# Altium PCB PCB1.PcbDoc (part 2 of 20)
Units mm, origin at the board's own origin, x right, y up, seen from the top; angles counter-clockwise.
Board outline 294.51 x 138.18 mm, 12 copper layers (Top Layer 1 _Signal, L2_GND, L3_Signals, L4_GND, L5_POWER, L6_Signals, L7_GND, L8_Signals, L9_GND, L10_POWER, L11_GND, Bottom Layer_Signals), stack 1.788 mm thick; 1254 components, 836 nets, 5699 pads, 2073 vias.
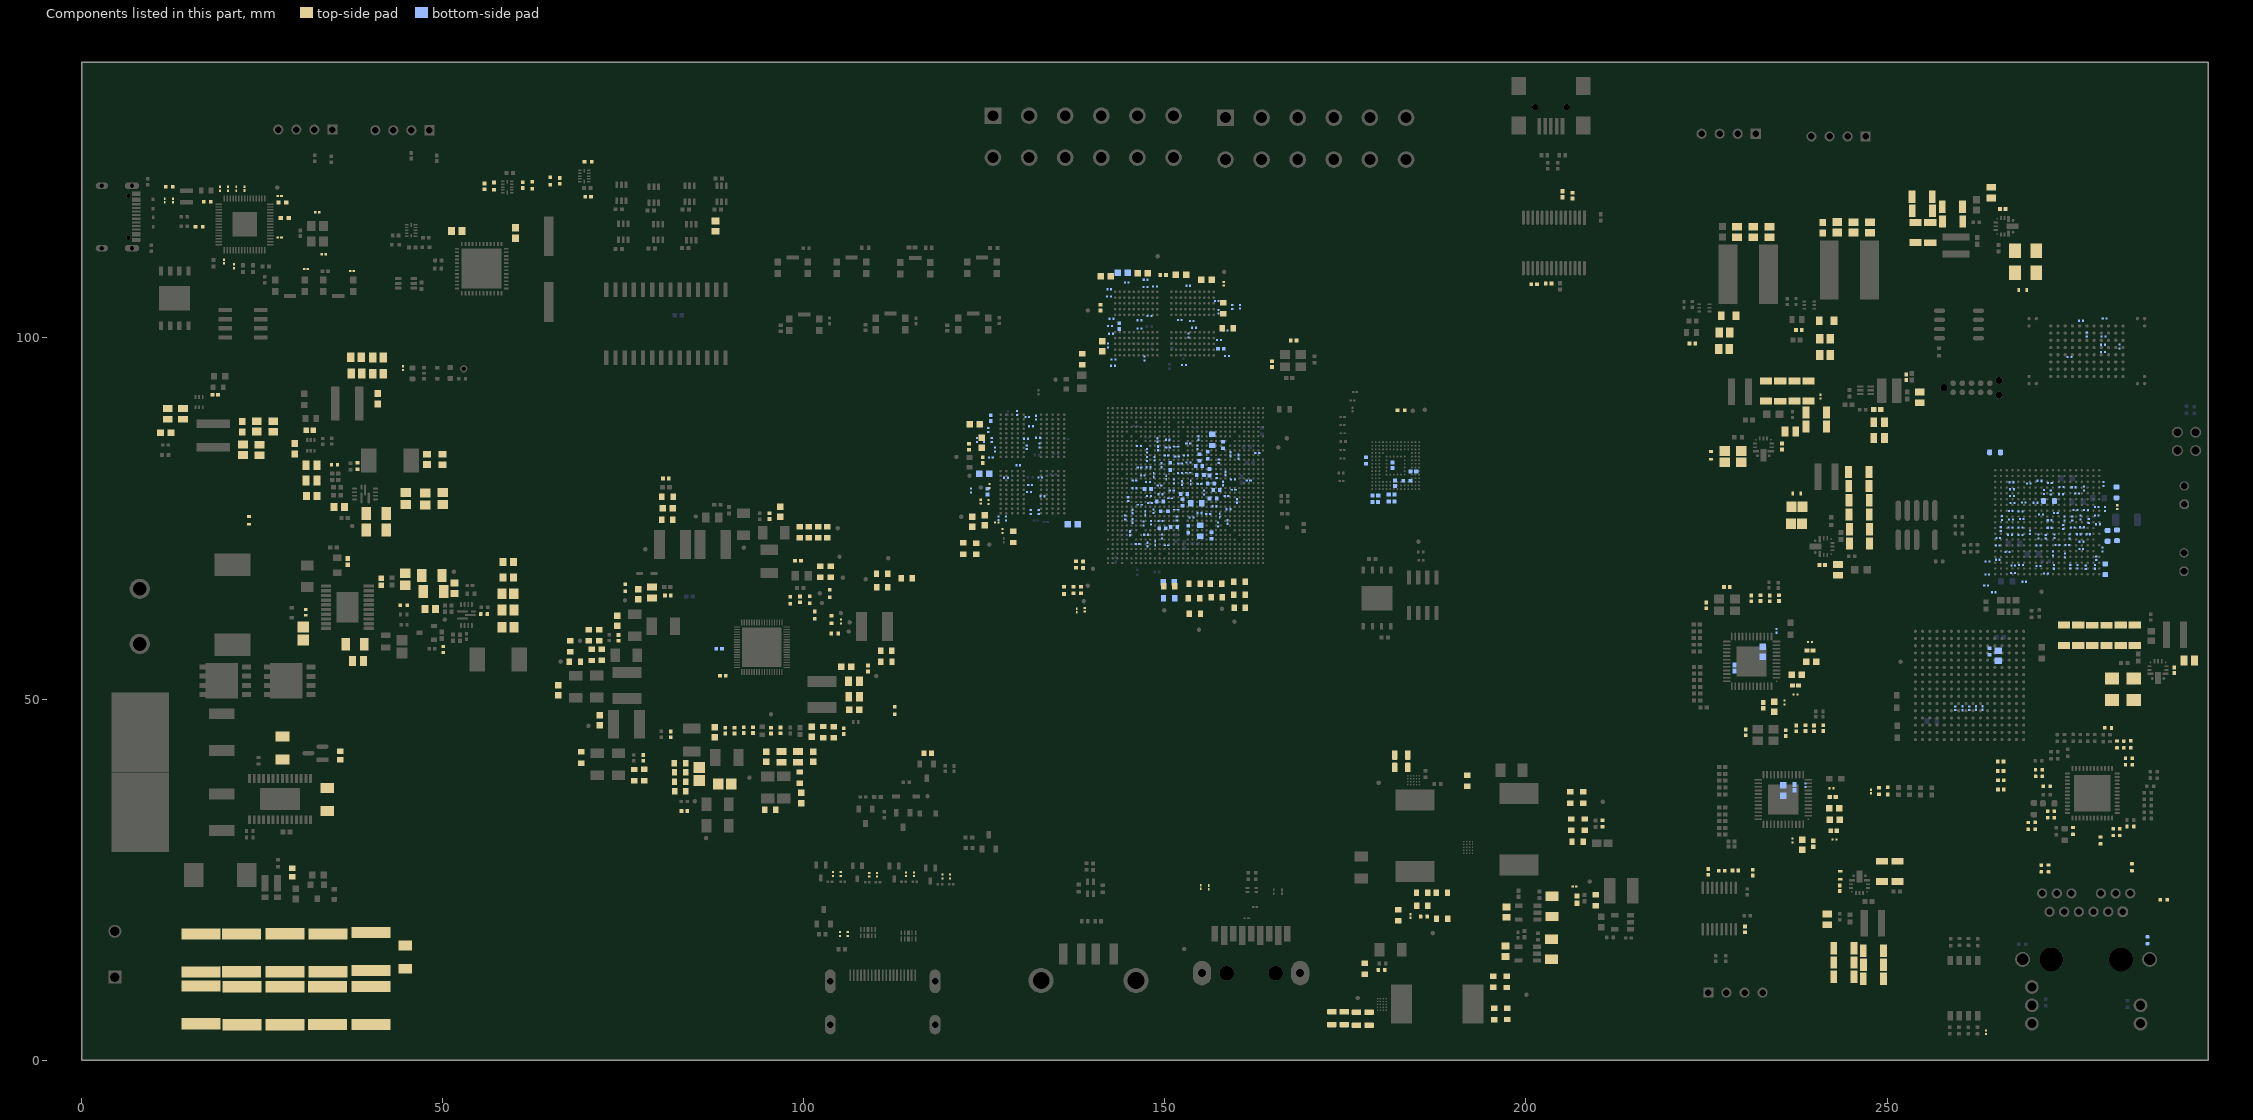
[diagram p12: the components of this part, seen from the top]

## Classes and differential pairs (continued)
differential pair DDR_CH0_CLK_B: +DDR_CH0_CLK_B_P -DDR_CH0_CLK_B_N
differential pair DDR_CH0_CLK_A: +DDR_CH0_CLK_A_P -DDR_CH0_CLK_A_N
differential pair USB: +USB_P -USB_N
differential pair _USB_: +_USB__P -_USB__N
differential pair TYPEC1_OTG_D: +TYPEC1_OTG_D_P -TYPEC1_OTG_D_N
differential pair RPD: +RPD_P -RPD_N
differential pair RP_D: +RP_D_P -RP_D_N
differential pair PCIE_TX_C: +PCIE_TX_C_P -PCIE_TX_C_N
differential pair PCIE_RX: +PCIE_RX_P -PCIE_RX_N
differential pair CK_LAN: +CK_LAN_P -CK_LAN_N
differential pair PCIE_TX: +PCIE_TX_P -PCIE_TX_N
differential pair PCIE_CLK: +PCIE_CLK_P -PCIE_CLK_N
differential pair P28.D: +P28.D_P -P28.D_N
differential pair P28.C: +P28.C_P -P28.C_N
differential pair P28.B: +P28.B_P -P28.B_N
differential pair P28.A: +P28.A_P -P28.A_N

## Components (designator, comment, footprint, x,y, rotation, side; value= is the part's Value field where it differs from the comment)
1 "10uf/1206" CAPC3216X180X50NL20T25 40.806,73.389 r180 top value=10µF
2 "10uf/1206" CAPC3216X180X50NL20T25 40.796,75.72 r180 top value=10µF
3 "10uf/1206" CAPC3216X180X50NL20T25 48.733,64.921 r0 top value=10µF
4 "10uf/1206" CAPC3216X180X50NL20T25 48.505,67.089 r0 top value=10µF
5 "10uf/1206" CAPC3216X180X50NL20T25 203.551,15.353 r270 top value=10µF
6 "10uf/1206" CAPC3216X180X50NL20T25 203.639,21.286 r270 top value=10µF
C1 "0.1uf / 0201" FP-CC0201-BB-MFG 263.908,69.036 r180 bottom
C2 "0.1uf / 0201" FP-CC0201-BB-MFG 263.874,67.254 r0 bottom
C3 "0.1uf / 0201" FP-CC0201-BB-MFG 267.45,67.447 r180 bottom
C4 "0.1uf / 0201" FP-CC0201-BB-MFG 269,66.227 r180 bottom
C5 "100nf/0201" FP-CL03-IPC_C 160.195,83.535 r90 bottom
C6 "1uf/0201" FP-CC0201-BA-MFG 280.137,102.692 r0 bottom value="1 uF"
C7 "1uf/0201" FP-CC0201-BA-MFG 279.902,98.048 r0 bottom value="1 uF"
C8 "1uf/0201" FP-CC0201-BA-MFG 279.885,99.051 r0 bottom value="1 uF"
C9 "1uf/0201" FP-CC0201-BA-MFG 279.971,100.219 r0 bottom value="1 uF"
C10 "1uf/0201" FP-CC0201-BA-MFG 282.191,98.826 r90 bottom value="1 uF"
C11 "1uf/0201" FP-CC0201-BA-MFG 275.252,97.358 r0 bottom value="1 uF"
C12 "1uf/0201" FP-CC0201-BA-MFG 263.705,3.857 r270 top value="1 uF"
C13 "1uf/0201" FP-CC0201-BA-MFG 277.66,100.491 r90 bottom value="1 uF"
C14 "1uf/0201" FP-CC0201-BA-MFG 276.878,102.382 r180 bottom value="1 uF"
C15 "100nf/0201" FP-CL03-IPC_C 158.517,78.135 r0 bottom
C16 "100nf/0201" FP-CL03-IPC_C 137.804,62.255 r90 top
C17 "100nf/0201" FP-CL03-IPC_C 146.218,71.489 r0 bottom
C18 "22uf/0603" FP-GRM188-0_2-MFG 150.602,65.622 r180 top
C19 "56pf 0402" CAPC1005X56X25LL10T15 18.514,92.133 r180 top
C20 "10uf 0805" FP-C0805C106K3PACTU-MFG 11.925,89.497 r270 top
C21 "10uf 0805" FP-C0805C106K3PACTU-MFG 14.049,89.488 r270 top
C22 "100nf 0603" FP-GRM188-0_1-e0_2_0_5-IPC_B 11.647,86.868 r0 top
C23 "100nf/0201" FP-CL03-IPC_C 161.606,80.25 r0 bottom
C24 "10uf/0603" FP-CC0603-DC-MFG 235.619,37.338 r270 bottom
C25 "10uf/0603" FP-CC0603-DC-MFG 242.772,33.275 r0 top
C26 "10uf/0603" FP-CC0603-DC-MFG 242.697,34.907 r0 top
C27 "1uf/0402" FP-C0402C-BB-IPC_B 237.192,37.772 r90 bottom
C28 "0.1uf / 0201" FP-CC0201-BB-MFG 238.697,38.057 r270 bottom
C29 "10uf/0603" FP-CC0603-DC-MFG 238.261,29.823 r270 top
C30 "100nf/0201" FP-CL03-IPC_C 162.792,84.077 r0 bottom
C31 "18pf/0402" FP-C0402-BB-MFG 164.827,96.371 r270 top value="18 pF"
C32 "100nf/0201" FP-CL03-IPC_C 145.525,75.978 r90 bottom
C33 "18pf/0402" FP-C0402-BB-MFG 167.818,99.647 r180 top value="18 pF"
C34 "100nf/0201" FP-CL03-IPC_C 157.597,75.402 r270 bottom
C35 "100nf/0201" FP-CL03-IPC_C 159.525,78.981 r0 bottom
C36 "22uf/0603" FP-GRM188-0_2-MFG 114.255,66.73 r0 top
C37 "22uf/0603" FP-GRM188-0_2-MFG 160.338,66.27 r0 top
C38 "22uf/0603" FP-GRM188-0_2-MFG 154.114,65.947 r180 top
C39 "GRM31CR71H475KA12L" FP-GRM31C-0_2-e0_3_0_8-IPC_C 37.854,57.563 r180 top
C40 "C0805C104M5RACTU" FP-C0805C-DN-MFG 38.265,55.279 r180 top value="0.10 μF"
C41 "22uf/0603" FP-GRM186-0_2-MFG 95.37,34.65 r0 top
C42 "22uf/0603" FP-GRM186-0_2-MFG 99.453,39.124 r270 top
C43 "47uf/0805" CAPC2013X145X50ML20T25 89.049,38.249 r180 top
C44 "47uf/0805" CAPC2013X145X50ML20T25 85.538,39.622 r90 top
C45 "1uf/0402" FP-C0402C105K8PACTU-MFG 81.576,45.093 r90 top
C46 "22uf/0603" FP-GRM186-0_2-MFG 69.211,41.901 r270 top
C47 "100nf 10V 0402" CAPC1005X55X25LL05T10 289.762,53.982 r270 top
C48 "0.47UF 10V X7R 0805" FP-C0805C-DN-MFG 291.848,55.342 r0 top value="0.47 μF"
C49 "10uf/0603" FP-CC0603-DC-MFG 107.001,48.494 r0 top
C50 "22uf/0805" FP-C0805C226M8PACTU-MFG 106.951,52.463 r0 top
C51 "1uf/0402" FP-C0402C105K8PACTU-MFG 77.786,41.84 r90 top
C52 "10uf/0603" FP-CC0603-DC-MFG 71.744,47.044 r90 top
C53 "22uf/0603" FP-GRM186-0_2-MFG 76.528,39.47 r270 top
C54 "22uf/0603" FP-GRM186-0_2-MFG 77.924,39.481 r270 top
C55 "100pf/0402" FP-C0402-BB-MFG 80.915,80.539 r0 top value="100 pF"
C56 "22uf/0603" FP-GRM186-0_2-MFG 81.13,78.032 r0 top
C57 "22uf/0603" FP-GRM186-0_2-MFG 81.102,74.816 r0 top
C58 "10uf/0603" FP-CC0603-DC-MFG 81.181,76.395 r0 top
C59 "10uf/0603" FP-CC0603-DC-MFG 77.102,64.513 r90 top
C60 "10uf/0603" FP-CC0603-DC-MFG 94.823,42.008 r270 top
C61 "22uf/0603" FP-GRM186-0_2-MFG 71.676,58.839 r90 top
C62 "1uf/0402" FP-C0402C105K8PACTU-MFG 74.344,58.465 r90 top
C63 "22uf/0603" FP-GRM186-0_2-MFG 103.706,67.622 r90 top
C64 "22uf/0603" FP-GRM186-0_2-MFG 102.277,67.608 r90 top
C65 "22uf/0603" FP-GRM186-0_2-MFG 70.255,58.823 r90 top
C66 "22uf/0603" FP-GRM186-0_2-MFG 70.663,56.112 r270 top
C67 "22uf/0603" FP-GRM186-0_2-MFG 72.025,56.136 r270 top
C68 "22uf/0805" FP-C0805C226M8PACTU-MFG 106.973,50.302 r0 top
C69 "100pf/0402" FP-C0402-BB-MFG 105.524,45.564 r270 top value="100 pF"
C70 "22uf/0603" FP-GRM186-0_2-MFG 104.121,45.413 r270 top
C71 "22uf/0603" FP-GRM186-0_2-MFG 102.725,45.423 r270 top
C72 "10uf/0603" FP-CC0603-DC-MFG 101.112,45.452 r270 top
C73 "22uf/0603" FP-GRM186-0_2-MFG 111.417,56.685 r0 top
C74 "22uf/0603" FP-GRM186-0_2-MFG 111.438,55.151 r0 top
C75 "10uf/0603" FP-CC0603-DC-MFG 105.884,54.452 r0 top
C76 "22uf/0603" FP-GRM186-0_2-MFG 82.906,37.216 r180 top
C77 "10uf/0603" FP-CC0603-DC-MFG 101.325,42.021 r270 top
C78 "1uf/0201" FP-CC0201-BA-MFG 265.752,73.562 r90 bottom value="1 uF"
C79 "1uf/0201" FP-CC0201-BA-MFG 267.181,74.843 r180 bottom value="1 uF"
C80 "1uf/0201" FP-CC0201-BA-MFG 267.312,78.114 r180 bottom value="1 uF"
C81 "1uf/0201" FP-CC0201-BA-MFG 266.666,70.343 r180 bottom value="1 uF"
C82 "1uf/0201" FP-CC0201-BA-MFG 267.289,79.05 r180 bottom value="1 uF"
C83 "1uf/0201" FP-CC0201-BA-MFG 267.109,73.77 r180 bottom value="1 uF"
C84 "1uf/0201" FP-CC0201-BA-MFG 267.029,72.746 r180 bottom value="1 uF"
C85 "1uf/0201" FP-CC0201-BA-MFG 265.897,75.051 r90 bottom value="1 uF"
C86 "1uf/0201" FP-CC0201-BA-MFG 267.373,77.148 r180 bottom value="1 uF"
C87 "1uf/0201" FP-CC0201-BA-MFG 267.133,76.02 r180 bottom value="1 uF"
C88 "Capacitor NP" CAP_C_0603 264.967,84.154 r180 bottom value=22uF
C89 "1uf/0201" FP-CC0201-BA-MFG 279.23,74.207 r0 bottom value="1 uF"
C90 "1uf/0201" FP-CC0201-BA-MFG 279.034,75.435 r0 bottom value="1 uF"
C91 "1uf/0201" FP-CC0201-BA-MFG 279.843,70.691 r90 bottom value="1 uF"
C92 "1uf/0201" FP-CC0201-BA-MFG 278.968,69.492 r90 bottom value="1 uF"
C93 "1uf/0201" FP-CC0201-BA-MFG 272.543,79.901 r180 bottom value="1 uF"
C94 "1uf/0201" FP-CC0201-BA-MFG 279.032,76.597 r0 bottom value="1 uF"
C95 "1uf/0201" FP-CC0201-BA-MFG 271.113,80.232 r180 bottom value="1 uF"
C96 "1uf/0201" FP-CC0201-BA-MFG 273.099,68.304 r270 bottom value="1 uF"
C97 "Capacitor NP" CAP_C_0603 281.773,78.606 r270 bottom value=22uF
C98 "1uf/0201" FP-CC0201-BA-MFG 277.935,74.658 r270 bottom value="1 uF"
C99 "1uf/0201" FP-CC0201-BA-MFG 275.842,79.335 r0 bottom value="1 uF"
C100 "1uf/0201" FP-CC0201-BA-MFG 275.379,68.31 r270 bottom value="1 uF"
C101 "1uf/0201" FP-CC0201-BA-MFG 278.786,68.305 r270 bottom value="1 uF"
C102 "1uf/0201" FP-CC0201-BA-MFG 272.005,67.378 r180 bottom value="1 uF"
C103 "1uf/0201" FP-CC0201-BA-MFG 277.525,68.256 r270 bottom value="1 uF"
C104 "1uf/0201" FP-CC0201-BA-MFG 274.167,79.369 r0 bottom value="1 uF"
C105 "1uf/0201" FP-CC0201-BA-MFG 277.282,79.135 r90 bottom value="1 uF"
C106 "Capacitor NP" CAP_C_0603 280.212,67.972 r90 bottom value=22uF
C107 "0.1uf / 0201" FP-CC0201-BB-MFG 269.631,79.82 r0 bottom
C108 "1uf/0201" FP-CC0201-BA-MFG 267.244,80.027 r180 bottom value="1 uF"
C109 "Capacitor NP" CAP_C_0201 268.553,68.567 r0 bottom value=0.1uF
C110 "Capacitor NP" CAP_C_0201 270.951,68.415 r0 bottom value=1uF
C111 "1uf/0201" FP-CC0201-BA-MFG 280.189,76.313 r270 bottom value="1 uF"
C112 "1uf/0201" FP-CC0201-BA-MFG 279.972,79.759 r90 bottom value="1 uF"
C113 "1uf/0201" FP-CC0201-BA-MFG 265.338,69.275 r180 bottom value="1 uF"
C114 "1uf/0201" FP-CC0201-BA-MFG 267.467,68.493 r180 bottom value="1 uF"
C115 "1uf/0201" FP-CC0201-BA-MFG 264.786,64.785 r180 bottom value="1 uF"
C116 "1uf/0201" FP-CC0201-BA-MFG 274.083,78.35 r180 bottom value="1 uF"
C117 "1uf/0201" FP-CC0201-BA-MFG 276.306,78.471 r0 bottom value="1 uF"
C118 "1uf/0201" FP-CC0201-BA-MFG 265.34,71.246 r180 bottom value="1 uF"
C119 "1uf/0201" FP-CC0201-BA-MFG 265.397,72.299 r180 bottom value="1 uF"
C120 "1uf/0201" FP-CC0201-BA-MFG 263.726,65.727 r180 bottom value="1 uF"
C121 "Capacitor NP" CAP_C_0603 272.433,77.423 r0 bottom value=22uF
C122 "1uf/0201" FP-CC0201-BA-MFG 274.946,71.344 r0 bottom value="1 uF"
C123 "1uf/0201" FP-CC0201-BA-MFG 273.608,71.309 r180 bottom value="1 uF"
C124 "1uf/0201" FP-CC0201-BA-MFG 271.307,75.564 r180 bottom value="1 uF"
C125 "1uf/0201" FP-CC0201-BA-MFG 272.521,74.761 r180 bottom value="1 uF"
C126 "1uf/0201" FP-CC0201-BA-MFG 272.521,73.711 r180 bottom value="1 uF"
C127 "1uf/0201" FP-CC0201-BA-MFG 275.243,72.522 r90 bottom value="1 uF"
C128 "1uf/0201" FP-CC0201-BA-MFG 276.088,76.169 r0 bottom value="1 uF"
C129 "1uf/0201" FP-CC0201-BA-MFG 272.988,70.15 r270 bottom value="1 uF"
C130 "1uf/0201" FP-CC0201-BA-MFG 274.411,73.824 r90 bottom value="1 uF"
C131 "1uf/0201" FP-CC0201-BA-MFG 276.377,68.315 r270 bottom value="1 uF"
C132 "Capacitor NP" CAP_C_0603 281.836,72.671 r90 bottom value=22uF
C133 "Capacitor NP" CAP_C_0603 280.542,72.596 r90 bottom value=22uF
C134 "1uf/0201" FP-CC0201-BA-MFG 271.723,78.649 r90 bottom value="1 uF"
C135 "1uf/0201" FP-CC0201-BA-MFG 272.664,78.598 r90 bottom value="1 uF"
C136 "1uf/0201" FP-CC0201-BA-MFG 277.009,73.774 r0 bottom value="1 uF"
C137 "1uf/0201" FP-CC0201-BA-MFG 273.375,75.777 r0 bottom value="1 uF"
C138 "1uf/0201" FP-CC0201-BA-MFG 273.186,72.528 r270 bottom value="1 uF"
C139 "1uf/0201" FP-CC0201-BA-MFG 276.93,71.772 r180 bottom value="1 uF"
C140 "1uf/0201" FP-CC0201-BA-MFG 275.714,73.767 r180 bottom value="1 uF"
C141 "1uf/0201" FP-CC0201-BA-MFG 274.576,74.994 r270 bottom value="1 uF"
C142 "1uf/0201" FP-CC0201-BA-MFG 268.928,77.233 r180 bottom value="1 uF"
C143 "1uf/0201" FP-CC0201-BA-MFG 269.813,73.088 r270 bottom value="1 uF"
C144 "1uf/0201" FP-CC0201-BA-MFG 268.655,74.922 r180 bottom value="1 uF"
C145 "1uf/0201" FP-CC0201-BA-MFG 268.472,72.69 r180 bottom value="1 uF"
C146 "1uf/0201" FP-CC0201-BA-MFG 275.651,75.009 r270 bottom value="1 uF"
C147 "1uf/0201" FP-CC0201-BA-MFG 270.558,77.167 r180 bottom value="1 uF"
C148 "1uf/0201" FP-CC0201-BA-MFG 268.483,73.766 r180 bottom value="1 uF"
C149 "1uf/0201" FP-CC0201-BA-MFG 277.858,72.818 r0 bottom value="1 uF"
C150 "1uf/0201" FP-CC0201-BA-MFG 268.474,75.944 r180 bottom value="1 uF"
C151 "1uf/0201" FP-CC0201-BA-MFG 271.967,72.46 r270 bottom value="1 uF"
C152 "1uf/0201" FP-CC0201-BA-MFG 270.979,72.523 r270 bottom value="1 uF"
C153 "1uf/0201" FP-CC0201-BA-MFG 276.538,72.818 r180 bottom value="1 uF"
C154 "1uf/0201" FP-CC0201-BA-MFG 274.65,69.875 r270 bottom value="1 uF"
C155 "1uf/0201" FP-CC0201-BA-MFG 277.543,76.158 r0 bottom value="1 uF"
C156 "1uf/0201" FP-CC0201-BA-MFG 276.773,75.141 r270 bottom value="1 uF"
C157 "1uf/0402" FP-C0402C105K8PACTU-MFG 83.461,34.49 r180 top
C158 "22uf/0603" FP-GRM186-0_2-MFG 82.877,38.511 r180 top
C159 "22uf/0603" FP-GRM186-0_2-MFG 82.878,39.861 r180 top
C160 "22uf/0603" FP-GRM186-0_2-MFG 82.864,41.098 r180 top
C161 "22uf/0805" FP-C0805C226M8PACTU-MFG 96.899,41.988 r270 top
C162 "22uf/0603" FP-GRM186-0_2-MFG 103.248,73.081 r270 top
C163 "1uf/0402" FP-C0402C105K8PACTU-MFG 95.256,75.318 r270 top
C164 "22uf/0603" FP-GRM186-0_2-MFG 99.431,73.099 r270 top
C165 "22uf/0603" FP-GRM186-0_2-MFG 100.706,73.079 r270 top
C166 "22uf/0603" FP-GRM186-0_2-MFG 101.976,73.079 r270 top
C167 "2.2uf/0402" FP-CC0402-CC-MFG 104.3,59.079 r0 top
C168 "2.2uf/0402" FP-CC0402-CC-MFG 98.153,63.682 r90 top
C169 "2.2uf/0402" FP-CC0402-CC-MFG 100.843,63.752 r90 top
C170 "1nf/0402" CAPC1005X55X25LL05T05 108.876,54.22 r90 top
C171 "2.2uf/0402" FP-CC0402-CC-MFG 101.505,61.615 r90 top
C172 "2.2uf/0402" FP-CC0402-CC-MFG 103.84,61.004 r90 top
C173 "22uf/0805" FP-C0805C226M8PACTU-MFG 99.196,41.993 r270 top
C174 "1uf/0402" FP-C0402C105K8PACTU-MFG 99.2,69.141 r0 top
C175 "1uf/0402" FP-C0402C105K8PACTU-MFG 88.279,56.976 r180 bottom
C176 "1uf/0201" FP-CC0201-BA-MFG 105.166,60.734 r270 top value="1 uF"
C177 "1uf/0402" FP-C0402C105K8PACTU-MFG 95.465,45.637 r90 top
C178 "1uf/0402" FP-C0402C105K8PACTU-MFG 96.773,45.644 r90 top
C179 "4.7uf/0402" FP-CC0402-MFG 75.286,65.419 r90 top value="4.7 uF"
C180 "22uf/0603" FP-GRM186-0_2-MFG 68.314,55.175 r0 top
C181 "22uf/0603" FP-GRM186-0_2-MFG 67.639,57.309 r90 top
C182 "0.1uf/0201" FP-CC0201-BB-MFG 240.78,91.867 r90 top
C183 "1uf/0201" FP-CC0201-BA-MFG 281.87,76.567 r270 top value="1 uF"
C184 "22uf 1206 25V" FP-GRM31C-0_3-e0_3_0_8-IPC_A 281.15,51.36 r90 top
C185 "22uf 1206 25V" FP-GRM31C-0_3-e0_3_0_8-IPC_A 284.186,51.368 r90 top
C186 "100nf 10V 0402" CAPC1005X55X25LL05T10 243.46,23.813 r90 top
C187 "2.2 nF 0402" FP-CGA2B-IPC_B 243.522,25.604 r90 top
C188 "10UF 25V1206" FP-C1206C-EH-MFG 249.309,26.127 r90 top value=10uF
C189 "10UF 25V1206" FP-C1206C-EH-MFG 251.462,26.135 r90 top value=10uF
C190 "1uf/0201" FP-CC0201-BA-MFG 276.9,70.759 r180 bottom value="1 uF"
C191 "1uf/0201" FP-CC0201-BA-MFG 270.968,71.264 r180 bottom value="1 uF"
C192 "UMK105CG331JV-F" FP-0402-L_1_0_0_05-W_0_5-MFG 44.603,62.989 r0 top
C193 "GRM1555C1E6R8CA01D" CAPC1005X55X25NL05T10 36.878,69.028 r90 top value=6.8pF
C194 "1uf/0201" FP-CC0201-BA-MFG 44.492,95.814 r90 top value="1 uF"
C195 "100nf 10V 0402" CAPC1005X55X25LL05T10 235.458,84.968 r270 top
C196 "100nf/0603" CAPC1608X92X38ML15T08 47.831,83.174 r270 top
C197 "100nf/0603" CAPC1608X92X38ML15T08 49.957,83.168 r270 top
C198 "100nf/0603" CAPC1608X92X38ML15T08 48.29,62.464 r0 top
C199 "100nf/0603" CAPC1608X92X38ML15T08 59.093,66.834 r180 top
C200 "100nf/0603" CAPC1608X92X38ML15T08 59.093,68.962 r180 top
C201 "100nf/0603" CAPC1608X92X38ML15T08 51.606,65.349 r270 top
C202 "CAP 22uF 16V 1206(3216)" CAPC1206(3216)190_L 248.124,13.218 r180 top value=22uF
C203 "100nf/0201" FP-CL03-IPC_C 145.508,74.652 r270 bottom
C204 "100nf/0201" FP-CL03-IPC_C 158.681,74.499 r270 bottom
C205 "33nf" CAPC2013X145X48NL20T23 44.844,66.575 r270 top
C206 "33pf 0402" CAPC1005X55X25ML05T10 31.592,87.224 r0 top
C207 "Capacitor 0.1 uF +/- 5% 16 V 0402" CAPC1005X56X25LL10T15 181.506,82.371 r90 bottom value=100nF
C208 "Capacitor 0.1 uF +/- 5% 16 V 0402" CAPC1005X56X25LL10T15 184.418,81.494 r180 bottom value=100nF
C209 "CC0402MRX5R7BB475" FP-CC0402-MFG 183.519,80.211 r0 bottom value="4.7 uF"
C210 "Capacitor 0.1 uF +/- 5% 16 V 0402" CAPC1005X56X25LL10T15 181.392,77.357 r180 bottom value=100nF
C211 "Capacitor 0.1 uF +/- 5% 16 V 0402" CAPC1005X56X25LL10T15 179.149,78.155 r0 bottom value=100nF
C212 "CC0402MRX5R7BB475" FP-CC0402-MFG 182.716,89.96 r180 top value="4.7 uF"
C213 "Capacitor 0.1 uF +/- 5% 16 V 0402" CAPC1005X56X25LL10T15 181.401,78.296 r180 bottom value=100nF
C214 "Capacitor 0.1 uF +/- 5% 16 V 0402" CAPC1005X56X25LL10T15 179.135,77.284 r0 bottom value=100nF
C215 "1uf/0201" FP-CC0201-BA-MFG 159.43,80.394 r0 bottom value="1 uF"
C216 "Capacitor 2,2µF +/-20% 10V 0402" CAPC0402(1005)60_L 177.836,83.038 r90 bottom value=2.2µF
C217 "Capacitor 10 pF +/- 0.25 pF 50 V 0402" CAPC1005X55X30LL05T10 181.87,79.855 r90 bottom value=10pF
C218 "120pf" CAPC1005X55X30ML05T10 41.499,66.223 r90 top
C219 "08055D104KAT2A" CAPC2013X140X50ML20T25 30.697,59.061 r90 top value=100nf
C220 "10uf/0402" CAPC0402(1005)60_L 156.364,79.822 r180 bottom value=10µF
C221 "10uf/0402" CAPC0402(1005)60_L 157.129,78.951 r180 bottom value=10µF
C222 "4.7uf/0402" FP-CC0402-MFG 156.687,77.769 r0 bottom value="4.7 uF"
C223 "22uf/0603" FP-GRM188-0_2-MFG 110.851,67.314 r180 top
C224 "22uf/0603" FP-GRM188-0_2-MFG 110.876,65.463 r180 top
C225 "GRM155R61H105KE05D" FP-GRM155-0_1-MFG 31.044,61.996 r270 top value=1uf
C226 "100nf/0201" FP-CL03-IPC_C 154.804,79.759 r180 bottom
C227 "1uf/0201" FP-CC0201-BA-MFG 149.38,74.646 r180 bottom value="1 uF"
C228 "100nf/0201" FP-CL03-IPC_C 152.396,79.93 r90 bottom
C229 "1uf/0201" FP-CC0201-BA-MFG 155.43,78.589 r270 bottom value="1 uF"
C230 "10uf/0402" CAPC0402(1005)60_L 149.307,77.343 r0 bottom value=10µF
C231 "10uf/0402" CAPC0402(1005)60_L 147.633,79.083 r0 bottom value=10µF
C232 "10uf/0402" CAPC0402(1005)60_L 152.465,77.206 r90 bottom value=10µF
C233 "10uf/0402" CAPC0402(1005)60_L 149.662,73.648 r0 bottom value=10µF
C234 "22uf/0603" FP-GRM188-0_2-MFG 123.907,70.817 r270 top
C235 "22uf/0603" FP-GRM188-0_2-MFG 122.062,70.845 r270 top
C236 "1uf/0201" FP-CC0201-BA-MFG 149.398,78.348 r0 bottom value="1 uF"
C237 "22uf/0603" FP-GRM188-0_2-MFG 150.588,63.926 r180 bottom
C238 "22uf/0603" FP-GRM188-0_2-MFG 150.551,66.203 r180 bottom
C239 "4.7uf/0402" FP-CC0402-MFG 149.929,76.004 r180 bottom value="4.7 uF"
C240 "1uf/0201" FP-CC0201-BA-MFG 151.646,74.987 r270 bottom value="1 uF"
C241 "100nf/0201" FP-CL03-IPC_C 151.569,76.212 r0 bottom
C242 "100nf/0201" FP-CL03-IPC_C 150.719,77.797 r180 bottom
C243 "100nf/0201" FP-CL03-IPC_C 149.275,79.542 r180 bottom
C244 "100nf/0201" FP-CL03-IPC_C 150.185,80.666 r90 bottom
C245 "22uf/0603" FP-GRM188-0_2-MFG 157.082,65.941 r180 top
C246 "22uf/0603" FP-GRM188-0_2-MFG 157.191,64.118 r180 top
C247 "22uf/0603" FP-GRM188-0_2-MFG 154.361,77.092 r180 bottom
C248 "1uf/0201" FP-CC0201-BA-MFG 156.875,76.686 r0 bottom value="1 uF"
C249 "10uf/0402" CAPC0402(1005)60_L 156.452,72.659 r90 bottom value=10µF
C250 "100nf/0201" FP-CL03-IPC_C 156.015,75.61 r180 bottom
C251 "10uf/0402" CAPC0402(1005)60_L 156.155,81.395 r90 bottom value=10µF
C252 "10uf/0402" CAPC0402(1005)60_L 158.068,85.148 r270 bottom value=10µF
C253 "22uf/0603" FP-GRM188-0_2-MFG 160.34,64.466 r0 top
C254 "22uf/0603" FP-GRM188-0_2-MFG 160.368,62.631 r0 top
C255 "4.7uf/0402" FP-CC0402-MFG 155.941,83.744 r90 bottom value="4.7 uF"
C256 "1uf/0201" FP-CC0201-BA-MFG 157.186,80.887 r90 bottom value="1 uF"
C257 "1uf/0201" FP-CC0201-BA-MFG 157.46,82.924 r270 bottom value="1 uF"
C258 "100nf/0201" FP-CL03-IPC_C 158.056,79.845 r270 bottom
C259 "100nf/0201" FP-CL03-IPC_C 158.375,81.232 r270 bottom
C260 "1uf/0201" FP-CC0201-BA-MFG 152.101,81.308 r180 bottom value="1 uF"
C261 "100nf/0201" FP-CL03-IPC_C 153.246,81.327 r0 bottom
C262 "10uf/0402" CAPC0402(1005)60_L 151.263,73.821 r0 bottom value=10µF
C263 "10uf/0402" CAPC0402(1005)60_L 152.631,78.376 r180 bottom value=10µF
C264 "4.7uf/0402" FP-CC0402-MFG 153.217,73.508 r270 bottom value="4.7 uF"
C265 "1uf/0201" FP-CC0201-BA-MFG 153.677,75.115 r0 bottom value="1 uF"
C266 "1uf/0201" FP-CC0201-BA-MFG 154.79,75.732 r0 bottom value="1 uF"
C267 "22uf/0603" FP-GRM188-0_2-MFG 154.924,73.302 r270 bottom
C268 "22uf/0603" FP-GRM188-0_2-MFG 156.568,85.882 r90 bottom
C269 "100nf/0201" FP-CL03-IPC_C 150.955,78.881 r180 bottom
C270 "100nf/0201" FP-CL03-IPC_C 154.66,86.154 r90 bottom
C271 "10uf/0402" CAPC0402(1005)60_L 154.724,82.264 r180 bottom value=10µF
C272 "10uf/0402" CAPC0402(1005)60_L 154.795,83.46 r270 bottom value=10µF
C273 "22uf/0603" FP-GRM188-0_2-MFG 154.156,61.814 r180 top
C274 "22uf/0603" FP-GRM188-0_2-MFG 154.032,63.954 r180 top
C275 "1uf/0201" FP-CC0201-BA-MFG 157.353,74.163 r270 bottom value="1 uF"
C276 "4.7uf/0402" FP-CC0402-MFG 154.922,81.025 r0 bottom value="4.7 uF"
C277 "1uf/0201" FP-CC0201-BA-MFG 153.26,82.77 r0 bottom value="1 uF"
C278 "1uf/0201" FP-CC0201-BA-MFG 151.283,80.136 r90 bottom value="1 uF"
C279 "100nf/0201" FP-CL03-IPC_C 152.092,82.62 r180 bottom
C280 "100nf/0201" FP-CL03-IPC_C 153.58,79.984 r270 bottom
C281 "100nf/0201" FP-CL03-IPC_C 184.037,19.946 r90 top
C282 "1uf/0201" FP-CC0201-BA-MFG 147.813,78.105 r0 bottom value="1 uF"
C283 "10uf/0402" CAPC0402(1005)60_L 137.7,68.619 r270 top value=10µF
C284 "1uf/0201" FP-CC0201-BA-MFG 144.933,77.675 r270 bottom value="1 uF"
C285 "1uf/0201" FP-CC0201-BA-MFG 147.645,80.065 r180 bottom value="1 uF"
C286 "100nf/0201" FP-CL03-IPC_C 150.412,84.822 r0 bottom
C287 "100nf/0201" FP-CL03-IPC_C 146.471,82.05 r180 bottom
C288 "100nf/0201" FP-CL03-IPC_C 148.466,80.995 r90 bottom
C289 "10uf/0402" CAPC0402(1005)60_L 138.677,68.597 r270 top value=10µF
C290 "1uf/0201" FP-CC0201-BA-MFG 145.813,79.196 r180 bottom value="1 uF"
C291 "1uf/0201" FP-CC0201-BA-MFG 146.933,80.968 r0 bottom value="1 uF"
C292 "100nf/0201" FP-CL03-IPC_C 145.813,80.265 r0 bottom
C293 "100nf/0201" FP-CL03-IPC_C 149.05,84.713 r270 bottom
C294 "100nf/0201" FP-CL03-IPC_C 148.986,85.861 r90 bottom
C295 "1uf/0201" FP-CC0201-BA-MFG 150.393,85.912 r180 bottom value="1 uF"
C296 "1uf/0201" FP-CC0201-BA-MFG 154.535,84.865 r270 bottom value="1 uF"
C297 "100nf/0201" FP-CL03-IPC_C 151.566,84.937 r0 bottom
C298 "1uf/0201" FP-CC0201-BA-MFG 146.436,85.029 r0 bottom value="1 uF"
C299 "1uf/0201" FP-CC0201-BA-MFG 147.736,82.096 r180 bottom value="1 uF"
C300 "1uf/0201" FP-CC0201-BA-MFG 152.935,83.701 r0 bottom value="1 uF"
C301 "100nf/0201" FP-CL03-IPC_C 150.238,83.737 r0 bottom
C302 "1uf/0201" FP-CC0201-BA-MFG 147.519,84.379 r90 bottom value="1 uF"
C303 "1uf/0201" FP-CC0201-BA-MFG 147.542,83.226 r270 bottom value="1 uF"
C304 "10uf/0402" CAPC0402(1005)60_L 137.356,65.119 r90 top value=10µF
C305 "1uf/0201" FP-CC0201-BA-MFG 138.908,62.368 r90 top value="1 uF"
C306 "4.7uf/0402" FP-CC0402-MFG 150.732,82.206 r270 bottom value="4.7 uF"
C307 "100nf/0201" FP-CL03-IPC_C 149.553,82.368 r270 bottom
C308 "1uf/0201" FP-CC0201-BA-MFG 148.58,83.263 r270 bottom value="1 uF"
C309 "10uf/0402" CAPC0402(1005)60_L 138.366,65.107 r90 top value=10µF
C310 "1uf/0201" FP-CC0201-BA-MFG 147.065,74.287 r270 bottom value="1 uF"
C311 "4.7uf/0402" FP-CC0402-MFG 136.036,65.041 r270 top value="4.7 uF"
C312 "100nf/0201" FP-CL03-IPC_C 151.658,83.572 r0 bottom
C313 "Capacitor NP" CAP_C_0402 282.231,31.579 r270 top value=0.1uF
C314 "1nf/0402" CAPC1005X55X25LL05T05 81.183,64.346 r0 top
C315 "10uf/0603" FP-CC0603-DC-MFG 152.241,108.747 r180 top
C316 "10uf/0603" FP-CC0603-DC-MFG 146.92,108.922 r0 top
C317 "100nf/0201" FP-CC0201-BA-MFG 152.659,96.255 r180 bottom value="100 nF"
C318 "100nf/0201" FP-CC0201-BA-MFG 147.889,103.027 r0 bottom value="100 nF"
C319 "100nf/0201" FP-CC0201-BA-MFG 152.057,102.479 r180 bottom value="100 nF"
C320 "100nf/0201" FP-CC0201-BA-MFG 153.228,107.235 r180 bottom value="100 nF"
C321 "C0805C106K3PACTU" FP-C0805C106K3PACTU-MFG 31.834,82.371 r0 top
C322 "100nf/0201" FP-CC0201-BA-MFG 158.155,107.498 r270 top value="100 nF"
C323 "100nf/0201" FP-CC0201-BA-MFG 147.342,108.066 r0 bottom value="100 nF"
C324 "100nf/0201" FP-CC0201-BA-MFG 147.17,97.141 r270 bottom value="100 nF"
C325 "1uf/0402" FP-C0402C105K8PACTU-MFG 149.775,108.727 r0 top
C326 "C0805C106K3PACTU" FP-C0805C106K3PACTU-MFG 31.837,80.272 r0 top
C327 "100nf/0201" FP-CC0201-BA-MFG 146.469,101.324 r180 bottom value="100 nF"
C328 "100nf/0201" FP-CC0201-BA-MFG 146.492,102.443 r0 bottom value="100 nF"
C329 "100nf 0603" FP-GRM188-0_1-e0_2_0_5-IPC_B 29.513,84.627 r90 top
C330 "100nf 0603" FP-GRM188-0_1-e0_2_0_5-IPC_B 41.018,91.567 r270 top
C331 "100nf/0201" FP-CC0201-BA-MFG 158.402,101.052 r0 bottom value="100 nF"
C332 "100nf/0201" FP-CC0201-BA-MFG 153.732,102.35 r0 bottom value="100 nF"
C333 "100nf/0201" FP-CC0201-BA-MFG 157.407,103.62 r270 bottom value="100 nF"
C334 "100nf/0201" FP-CC0201-BA-MFG 142.128,98.97 r270 bottom value="100 nF"
C335 "100nf/0201" FP-CC0201-BA-MFG 154.031,101.407 r0 bottom value="100 nF"
C336 "100nf/0201" FP-CC0201-BA-MFG 148.638,107.138 r0 bottom value="100 nF"
C337 "100nf/0201" FP-CC0201-BA-MFG 147.314,107.062 r180 bottom value="100 nF"
C338 "22uf/0603" FP-GRM186-0_2-MFG 158.716,101.306 r0 top
C339 "10uf/0603" FP-CC0603-DC-MFG 144.188,109.027 r180 bottom
C340 "10uf/0603" FP-CC0603-DC-MFG 141.306,98.86 r270 top
C341 "1uf/0402" FP-C0402C105K8PACTU-MFG 141.074,104.211 r90 top
C342 "100nf/0201" FP-CC0201-BA-MFG 157.506,99.7 r0 bottom value="100 nF"
C343 "GRM21BR61A226ME44L" FP-GRM21B-0_2-e0_2_0_7-IPC_C 26.529,87.757 r270 top
C344 "100nf/0201" FP-CC0201-BA-MFG 142.56,100.568 r180 bottom value="100 nF"
C345 "100nf/0201" FP-CC0201-BA-MFG 159.341,104.297 r270 bottom value="100 nF"
C346 "100nf/0201" FP-CC0201-BA-MFG 142.837,96.158 r180 bottom value="100 nF"
C347 "2.2 nF 0402" FP-CGA2B-IPC_B 225.608,83.737 r270 top
C348 "10uf 0805" FP-C0805C106K3PACTU-MFG 248.905,86.159 r0 top
C349 "6.8μF 35V 0805" FP-C2012-125-0_2-IPC_B 229.841,83.549 r270 top
C350 "10uf/0603" FP-CC0603-DC-MFG 99.639,36.288 r90 top
C351 "6.8μF 35V 0805" FP-C2012-125-0_2-IPC_B 227.502,83.549 r270 top
C352 "GRM21BR61A226ME44L" FP-GRM21B-0_2-e0_2_0_7-IPC_C 24.614,84.468 r90 top
C353 "CAP 22uF 16V 1206(3216)" CAPC1206(3216)190_L 240.195,89.684 r180 top value=22uF
C354 "10uf 0805" FP-C0805C106K3PACTU-MFG 248.907,88.331 r0 top
C355 "56nf 0402 16V" CAPC1005X55X25ML05T10 248.638,90.103 r180 top
C356 "100nf/0201" FP-CC0201-BA-MFG 142.888,97.036 r180 bottom value="100 nF"
C357 "100nf/0201" FP-CC0201-BA-MFG 157.18,105.102 r0 bottom value="100 nF"
C358 "100nf/0201" FP-CC0201-BA-MFG 160.389,104.319 r270 bottom value="100 nF"
C359 "100nf/0201" FP-CC0201-BA-MFG 142.418,101.654 r180 bottom value="100 nF"
C360 "100nf/0201" FP-CC0201-BA-MFG 158.621,97.507 r0 bottom value="100 nF"
C361 "100nf/0201" FP-CC0201-BA-MFG 153.254,100.339 r90 bottom value="100 nF"
C362 "100nf/0201" FP-CC0201-BA-MFG 142.307,106.734 r180 bottom value="100 nF"
C363 "100nf/0201" FP-CC0201-BA-MFG 144.714,107.678 r180 bottom value="100 nF"
C364 "100nf/0201" FP-CC0201-BA-MFG 142.282,105.755 r180 bottom value="100 nF"
C365 "100nf/0201" FP-CC0201-BA-MFG 142.595,102.653 r180 bottom value="100 nF"
C366 "22uf/0603" FP-GRM186-0_2-MFG 158.106,104.099 r270 top
C367 "10uf/0603" FP-CC0603-DC-MFG 141.824,108.56 r180 top
C368 "10uf/0603" FP-CC0603-DC-MFG 155.761,108.074 r0 top
C369 "Capacitor NP" CAP_C_0402 271.365,26.53 r90 top value=0.1uF
C370 "Capacitor NP" CAP_C_0402 272.362,26.545 r90 top value=0.1uF
C371 "Capacitor NP" CAP_C_0402 288.317,22.187 r0 top value=0.1uF
C372 "Capacitor NP" CAP_C_0402 272.702,34.476 r180 top value=0.1uF
C373 "Capacitor NP" CAP_C_0402 272.702,33.562 r180 top value=4.7uF
C374 "Capacitor NP" CAP_C_0402 283.91,26.705 r90 top value=0.1uF
C375 "Capacitor NP" CAP_C_0402 271.041,39.295 r180 top value=0.1uF
C376 "Capacitor NP" CAP_C_0402 281.842,43.713 r90 top value=0.1uF
C377 "Capacitor NP" CAP_C_0402 282.795,43.707 r90 top value=0.1uF
C378 "Capacitor NP" CAP_C_0402 283.733,43.727 r90 top value=0.1uF
C379 "Capacitor NP" CAP_C_0402 271.036,40.209 r180 top value=4.7uF
C380 "Capacitor NP" CAP_C_0402 286.075,16.602 r90 bottom value=0.1uF
C381 "Capacitor NP" CAP_C_0402 283.704,32.345 r180 top value=0.1uF
C382 "Capacitor NP" CAP_C_0402 283.499,40.887 r0 top value=0.1uF
C383 "Capacitor NP" CAP_C_0402 283.499,41.795 r0 top value=0.1uF
C384 "Capacitor NP" CAP_C_0402 280.612,45.999 r0 top value=0.1uF
C385 "Capacitor NP" CAP_C_0402 272.097,37.913 r180 top value=0.1uF
C386 "Capacitor NP" CAP_C_0402 275.753,31.731 r270 top value=4.7uF
C387 "Capacitor NP" CAP_C_0402 281.334,31.578 r270 top value=0.1uF
C388 "1uf/0402" FP-C0402C105K8PACTU-MFG 157.741,98.504 r0 bottom
C389 "Capacitor NP" CAP_C_0402 269.536,32.429 r270 top value=0.1uF
C390 "Capacitor NP" CAP_C_0402 270.518,32.437 r270 top value=4.7uF
C391 "Capacitor NP" CAP_C_0402 279.561,30.422 r270 top value=0.1uF
C392 "1uf/0402" FP-C0402C105K8PACTU-MFG 143.681,101.649 r270 bottom
C393 "10uf/0603" FP-CC0603-DC-MFG 123.649,88.018 r180 top
C394 "10uf/0603" FP-CC0603-DC-MFG 137.245,74.178 r0 bottom
C395 "100nf/0201" FP-CC0201-BA-MFG 125.724,79.515 r90 top value="100 nF"
C396 "100nf/0201" FP-CC0201-BA-MFG 132.744,80.685 r180 bottom value="100 nF"
C397 "100nf/0201" FP-CC0201-BA-MFG 124.967,85.867 r270 bottom value="100 nF"
C398 "100nf/0201" FP-CC0201-BA-MFG 123.965,85.849 r270 bottom value="100 nF"
C399 "100nf/0201" FP-CC0201-BA-MFG 126.034,85.886 r270 bottom value="100 nF"
C400 "100nf/0201" FP-CC0201-BA-MFG 131.348,79.624 r0 bottom value="100 nF"
C401 "100nf/0201" FP-CC0201-BA-MFG 127.508,73.265 r270 top value="100 nF"
C402 "1uf/0402" FP-C0402C105K8PACTU-MFG 122.878,84.931 r90 top
C403 "100nf/0201" FP-CC0201-BA-MFG 125.904,83.442 r180 bottom value="100 nF"
C404 "100nf/0201" FP-CC0201-BA-MFG 126.489,84.532 r270 bottom value="100 nF"
C405 "100nf/0201" FP-CC0201-BA-MFG 130.786,86.05 r180 bottom value="100 nF"
C406 "100nf/0201" FP-CC0201-BA-MFG 130.876,84.857 r90 bottom value="100 nF"
C407 "100nf/0201" FP-CC0201-BA-MFG 132.454,86.187 r180 bottom value="100 nF"
C408 "100nf/0201" FP-CC0201-BA-MFG 128.001,80.634 r180 bottom value="100 nF"
C409 "100nf/0201" FP-CC0201-BA-MFG 132.664,85.091 r90 bottom value="100 nF"
C410 "100nf/0201" FP-CC0201-BA-MFG 126.711,74.464 r180 top value="100 nF"
C411 "100nf/0201" FP-CC0201-BA-MFG 129.689,82.364 r0 bottom value="100 nF"
C412 "22uf/0603" FP-GRM186-0_2-MFG 128.994,72.453 r270 top
C413 "10uf/0603" FP-CC0603-DC-MFG 124.97,81.195 r180 bottom
C414 "10uf/0603" FP-CC0603-DC-MFG 124.646,85.465 r90 top
C415 "1uf/0402" FP-C0402C105K8PACTU-MFG 124.772,83.079 r270 top
C416 "100nf/0201" FP-CC0201-BA-MFG 133.046,78.074 r0 bottom value="100 nF"
C417 "100nf/0201" FP-CC0201-BA-MFG 124.501,77.329 r270 top value="100 nF"
C418 "100nf/0201" FP-CC0201-BA-MFG 131.206,78.643 r180 bottom value="100 nF"
C419 "100nf/0201" FP-CC0201-BA-MFG 126.966,75.025 r270 bottom value="100 nF"
C420 "100nf/0201" FP-CC0201-BA-MFG 125.571,77.3 r270 top value="100 nF"
C421 "100nf/0201" FP-CC0201-BA-MFG 127.991,75.008 r270 bottom value="100 nF"
C422 "100nf/0201" FP-CC0201-BA-MFG 132.138,88.958 r90 bottom value="100 nF"
C423 "100nf/0201" FP-CC0201-BA-MFG 132.539,75.906 r270 bottom value="100 nF"
C424 "100nf/0201" FP-CC0201-BA-MFG 123.168,78.883 r90 bottom value="100 nF"
C425 "100nf/0201" FP-CC0201-BA-MFG 131.483,87.76 r0 bottom value="100 nF"
C426 "100nf/0201" FP-CC0201-BA-MFG 131.435,75.893 r270 bottom value="100 nF"
C427 "100nf/0201" FP-CC0201-BA-MFG 129.546,89.584 r90 bottom value="100 nF"
C428 "100nf/0201" FP-CC0201-BA-MFG 130.948,89.055 r180 bottom value="100 nF"
C429 "100nf/0201" FP-CC0201-BA-MFG 125.549,87.26 r270 bottom value="100 nF"
C430 "22uf/0603" FP-GRM186-0_2-MFG 138.566,97.042 r90 top
C431 "10uf/0603" FP-CC0603-DC-MFG 123.357,74.564 r270 top
C432 "10uf/0603" FP-CC0603-DC-MFG 125.089,74.743 r270 top
C433 "1uf/0402" FP-C0402C105K8PACTU-MFG 125.885,88.882 r90 bottom
C434 "100nf/0603" CAPC1608X92X38ML15T08 35.663,76.591 r180 top
C435 "100nf/0603" CAPC1608X92X38ML15T08 31.849,78.123 r180 top
C436 "220nf/0402" CAPC0402(1005)60_L 38.176,82.275 r90 top value=F
C437 "GRM21BR61A226ME44L" FP-GRM21B-0_2-e0_2_0_7-IPC_C 24.255,87.763 r270 top
C438 "22uf 0805 16V" FP-GRM21B-0_2-e0_2_0_7-IPC_C 38.041,95.077 r180 top
C439 "1uf/ 0402" FP-GRM15-0_1-MFG 35.01,82.432 r180 top value=1uF
C440 "22uf/0805" FP-GRM21B-0_2-e0_2_0_7-IPC_B 50.033,77.764 r270 top
C441 "22uf/0805" FP-GRM21B-0_2-e0_2_0_7-IPC_B 47.56,77.687 r270 top
C442 "10uf/0603" FP-CC0603-DC-MFG 74.177,60.85 r90 top
C443 "22uf/0805" FP-GRM21B-0_2-e0_2_0_7-IPC_B 44.87,77.766 r270 top
C444 "10uf/0603" FP-CC0603-DC-MFG 87.64,45.405 r270 top
C445 "220nf/0402" CAPC0402(1005)60_L 55.739,61.746 r0 top value=F
C446 "10uf/0603" FP-CC0603-DC-MFG 96.775,75.916 r90 top
C447 "22uf 0805 16V" FP-GRM21B-0_2-e0_2_0_7-IPC_C 38.014,97.312 r180 top
C448 "1uf/ 0402" FP-GRM15-0_1-MFG 50.068,56.858 r270 top value=1uF
C449 "22uf/0805" FP-GRM21B-0_2-e0_2_0_7-IPC_B 59.017,64.572 r0 top
C450 "22uf/0805" FP-GRM21B-0_2-e0_2_0_7-IPC_B 59.067,62.327 r0 top
C451 "1uf 16V 0402" FP-0402-L_1_0_1-W_0_5_0_1-MFG 28.142,116.61 r180 top
C452 "22uf/0805" FP-GRM21B-0_2-e0_2_0_7-IPC_B 59.046,59.942 r0 top
C453 "1uf 16V 0402" FP-0402-L_1_0_1-W_0_5_0_1-MFG 27.808,118.757 r180 top
C454 "100nf/0201" FP-CL03-IPC_C 147.573,71.379 r270 bottom
C455 "100nf/0201" FP-CL03-IPC_C 159.086,83.902 r270 bottom
C456 "100nf/0201" FP-CL03-IPC_C 145.15,72.943 r270 bottom
C457 "100nf/0201" FP-CL03-IPC_C 156.081,23.927 r270 top
C458 "100nf/0201" FP-CL03-IPC_C 154.964,23.974 r270 top
C459 "100nf/0201" FP-CL03-IPC_C 150.241,71.287 r0 bottom
C460 "1uf/0201" FP-CC0201-BA-MFG 149.612,72.493 r90 bottom value="1 uF"
C461 "100nf/0201" FP-CL03-IPC_C 153.25,85.362 r0 bottom
C462 "1uf/0201" FP-CC0201-BA-MFG 148.087,74.403 r270 bottom value="1 uF"
C463 "4.7uf/0402" FP-CC0402-MFG 103.589,64.615 r90 top value="4.7 uF"
C464 "100nf/0201" FP-CL03-IPC_C 147.281,75.734 r270 bottom
C465 "1uf/0201" FP-CC0201-BA-MFG 106.082,17.478 r90 top value="1 uF"
C466 "1uf/0201" FP-CC0201-BA-MFG 158.795,76.267 r0 bottom value="1 uF"
C467 "4.7uf/0402" FP-CC0402-MFG 112.586,48.408 r270 top value="4.7 uF"
C468 "100nf/0201" FP-CL03-IPC_C 160.007,77.407 r90 bottom
C469 "1uf/0201" FP-CC0201-BA-MFG 105.035,17.483 r90 top value="1 uF"
C470 "1uf/0201" FP-CC0201-BA-MFG 148.431,75.992 r270 bottom value="1 uF"
C471 "1uf/0201" FP-CC0201-BA-MFG 147.368,72.739 r0 bottom value="1 uF"
C472 "1uf/0201" FP-CC0201-BA-MFG 144.514,75.116 r270 bottom value="1 uF"
C473 "100nf/0201" FP-CL03-IPC_C 148.67,71.568 r270 bottom
C474 "220nf/0201" FP-CC0201-BA-MFG 120.261,25.424 r270 top value="220 nF"
C475 "220nf/0201" FP-CC0201-BA-MFG 119.2,25.441 r270 top value="220 nF"
C476 "220nf/0201" FP-CC0201-BA-MFG 115.26,25.734 r270 top value="220 nF"
C477 "220nf/0201" FP-CC0201-BA-MFG 114.173,25.729 r270 top value="220 nF"
C478 "220nf/0201" FP-CC0201-BA-MFG 110.126,25.669 r270 top value="220 nF"
C479 "220nf/0201" FP-CC0201-BA-MFG 109.074,25.667 r270 top value="220 nF"
C480 "220nf/0201" FP-CC0201-BA-MFG 105.116,25.756 r270 top value="220 nF"
C481 "220nf/0201" FP-CC0201-BA-MFG 104.044,25.764 r270 top value="220 nF"
C482 "100pf/0402" CAPC1005X55X25ML05T05 117.177,42.489 r0 top
C483 "22uf 0805 16V" FP-GRM21B-0_2-e0_2_0_7-IPC_C 41.05,95.03 r0 top
C484 "22uf 0805 16V" FP-GRM21B-0_2-e0_2_0_7-IPC_C 41.05,97.293 r0 top
C485 "22UF/0805" CAPC0805(2012)145_L 174.839,5.808 r90 top
C486 "C0805C226M8PACTU" FP-C0805C226M8PACTU-MFG 254.522,91.774 r270 top
C487 "100nf" CAPC1005X55X25LL05T10 252.675,94.549 r270 top
C488 "GRM21BR61A226ME44L" FP-GRM21B-0_2-e0_2_0_7-IPC_C 22.363,84.514 r90 top
C489 "100nf 0603" FP-GRM188-0_1-e0_2_0_5-IPC_B 22.271,87.705 r90 top
C490 "CAP 22uF 16V 1206(3216)" CAPC1206(3216)190_L 248.101,11.253 r180 top value=22uF
C491 "CAP 22uF 16V 1206(3216)" CAPC1206(3216)190_L 284.298,58.835 r270 top value=22uF
C492 "2.2 nF 0402" FP-CGA2B-IPC_B 23.16,74.733 r90 top
C493 "22UF/0805" CAPC0805(2012)145_L 173.127,5.821 r90 top
C494 "22uf/0603" FP-GRM188-0_2-MFG 207.948,36.367 r90 top
C495 "22uf/0603" FP-GRM188-0_2-MFG 206.286,32.613 r270 top
C496 "22uf/0603" FP-GRM188-0_2-MFG 208.124,32.613 r270 top
C497 "22uf/0603" FP-GRM188-0_2-MFG 206.149,36.369 r90 top
C498 "22uf/0603" FP-GRM188-0_2-MFG 191.879,38.676 r270 top
C499 "1µF  0402" CAPC0402(1005)60_L 210.594,32.762 r90 top value=1µF
C500 "22UF/0805" CAPC0805(2012)145_L 176.519,5.739 r90 top
C501 "22UF/0805" CAPC0805(2012)145_L 178.276,5.737 r90 top
C502 "22uf/0603" FP-GRM188-0_2-MFG 195.488,10.854 r90 top
C503 "22uf/0603" FP-GRM188-0_2-MFG 197.337,10.834 r90 top
C504 "22uf/0603" FP-GRM188-0_2-MFG 195.603,6.384 r270 top
C505 "22uf/0603" FP-GRM188-0_2-MFG 197.44,6.395 r270 top
C506 "22uf/0603" FP-GRM188-0_2-MFG 177.672,12.663 r90 top
C507 "1µF  0402" CAPC0402(1005)60_L 180.008,12.503 r0 top value=1µF
C508 "22uf/0603" FP-GRM188-0_2-MFG 207.147,30.262 r180 top
C509 "22UF/0805" CAPC0805(2012)145_L 182.731,40.53 r0 top
C510 "22UF/0805" CAPC0805(2012)145_L 182.738,42.227 r0 top
C511 "22uf/0603" FP-GRM188-0_2-MFG 185.621,23.188 r180 top
C512 "22uf/0603" FP-GRM188-0_2-MFG 188.39,19.598 r0 top
C513 "22uf/0603" FP-GRM188-0_2-MFG 188.366,23.192 r0 top
C514 "22uf/0603" FP-GRM188-0_2-MFG 185.64,21.379 r180 top
C515 "22uf/0603" FP-GRM188-0_2-MFG 182.348,20.059 r90 top
C516 "1µF  0402" CAPC0402(1005)60_L 185.873,19.855 r0 top value=1µF
C517 "100pf/0402" CAPC1005X55X25ML05T05 207.049,22.221 r90 top
C518 "22uf/0603" FP-GRM188-0_2-MFG 209.638,22.129 r270 top
C519 "100nf/0201" FP-CL03-IPC_C 206.731,24.046 r180 top
C520 "100nf/0603" CAPC1608X92X38ML15T08 197.157,15.068 r270 top
C521 "100nf/0603" CAPC1608X92X38ML15T08 197.29,20.497 r270 top
C522 "CAP 22uF 16V 1206(3216)" CAPC1206(3216)190_L 248.101,15.16 r180 top value=22uF
C523 "CAP 22uF 16V 1206(3216)" CAPC1206(3216)190_L 244.024,15.505 r0 top value=22uF
C524 "CAP 22uF 16V 1206(3216)" CAPC1206(3216)190_L 244.016,11.556 r0 top value=22uF
C525 "CAP 22uF 16V 1206(3216)" CAPC1206(3216)190_L 244.029,13.518 r0 top value=22uF
C526 "0.47UF 10V X7R 0805" FP-C0805C-DN-MFG 241.724,19.488 r270 top value="0.47 μF"
C527 "100nf 10V 0402" CAPC1005X55X25LL05T10 266.027,117.851 r0 top
C528 "2.2 nF 0402" FP-CGA2B-IPC_B 268.803,106.656 r0 top
C529 "22uf 1206 25V" FP-GRM31C-0_3-e0_3_0_8-IPC_A 269.187,109.048 r180 top
C530 "22uf 1206 25V" FP-GRM31C-0_3-e0_3_0_8-IPC_A 269.187,112.089 r180 top
C531 "CAP 22uF 16V 1206(3216)" CAPC1206(3216)190_L 259.08,116.119 r180 top value=22uF
C532 "CAP 22uF 16V 1206(3216)" CAPC1206(3216)190_L 259.047,118.172 r180 top value=22uF
C533 "CAP 22uF 16V 1206(3216)" CAPC1206(3216)190_L 254.883,117.619 r0 top value=22uF
C534 "CAP 22uF 16V 1206(3216)" CAPC1206(3216)190_L 254.861,119.568 r0 top value=22uF
C535 "CAP 22uF 16V 1206(3216)" CAPC1206(3216)190_L 255.985,114.58 r90 top value=22uF
C536 "CAP 22uF 16V 1206(3216)" CAPC1206(3216)190_L 253.956,114.594 r90 top value=22uF
C537 "0.47UF 10V X7R 0805" FP-C0805C-DN-MFG 264.443,120.109 r90 top value="0.47 μF"
C538 "CAP 22uF 16V 1206(3216)" CAPC1206(3216)190_L 240.193,87.731 r180 top value=22uF
C539 "CAP 22uF 16V 1206(3216)" CAPC1206(3216)190_L 235.207,92.639 r270 top value=22uF
C540 "CAP 22uF 16V 1206(3216)" CAPC1206(3216)190_L 233.237,92.65 r270 top value=22uF
C541 "100nf/0402" FP-C0402-BB-MFG 203.152,107.534 r0 top value="0.10 μF"
C542 "4.7uf/0402" FP-CC0402-MFG 17.394,118.884 r180 top value="4.7 uF"
C543 "100nf/0402" FP-C0402-BB-MFG 206.43,119.7 r90 top value="0.10 μF"
C544 "1uf/0402" FP-C0402C-BB-IPC_B 205.073,119.892 r270 top
C545 "100nf/0402" FP-C0402-BB-MFG 201.137,107.448 r0 top value="0.10 μF"
C546 "100nf/0402" FP-C0402-BB-MFG 229.01,26.244 r180 top value="0.10 μF"
C547 "100nf/0402" FP-C0402-BB-MFG 230.328,18.097 r270 top value="0.10 μF"
C548 "100nf/0402" FP-C0402-BB-MFG 231.401,25.963 r90 top value="0.10 μF"
C549 "100nf/0402" FP-C0402-BB-MFG 227.114,26.223 r180 top value="0.10 μF"
C550 "100nf/0402" FP-C0402-BB-MFG 225.238,26.051 r90 top value="0.10 μF"
C551 "1uf/0402" FP-C0402C105K8PACTU-MFG 125.423,78.718 r90 bottom
C552 "22uf/0805" FP-C0805C226M8PACTU-MFG 78.985,64.749 r90 top
C553 "1uf/0402" FP-C0402C105K8PACTU-MFG 91.693,45.682 r270 top
C554 "1uf/0402" FP-C0402C105K8PACTU-MFG 99.485,63.813 r90 top
C555 "1uf/0402" FP-C0402C105K8PACTU-MFG 92.963,45.684 r90 top
C556 "1uf/0402" FP-C0402C105K8PACTU-MFG 90.412,45.632 r90 top
C557 "1uf/0402" FP-C0402C105K8PACTU-MFG 89.126,45.616 r90 top
C558 "1uf/0402" FP-C0402C105K8PACTU-MFG 88.786,53.208 r0 top
C559 "100nf/0201/25V" FP-CL03-IPC_C 31.07,109.547 r180 top
C560 "33PF 25V 0201" FP-C0201-AB-MFG 32.61,117.388 r0 top value="33 pF"
C561 "4.7uf/0402" FP-CC0402-MFG 12.131,120.933 r180 top value="4.7 uF"
C562 "100nf/0201/25V" FP-CL03-IPC_C 12.637,119.019 r270 top
C563 "33PF 25V 0201" FP-C0201-AB-MFG 33.534,111.574 r180 top value="33 pF"
C564 "100nf/0201/25V" FP-CL03-IPC_C 37.448,109.251 r0 top
C565 "100nf/0201/25V" FP-CL03-IPC_C 21.109,109.927 r90 top
C566 "100nf/0201/25V" FP-CL03-IPC_C 11.517,119.016 r270 top
C567 "4.7uf/0402" FP-CC0402-MFG 16.272,115.404 r180 top value="4.7 uF"
C568 "100nf/0201/25V" FP-CL03-IPC_C 19.162,120.662 r270 top
C569 "100nf/0201/25V" FP-CL03-IPC_C 19.717,110.566 r90 top
C570 "100nf/0201/25V" FP-CL03-IPC_C 27.427,113.931 r180 top
C571 "100nf/0201/25V" FP-CL03-IPC_C 21.414,120.66 r270 top
C572 "100nf/0201/25V" FP-CL03-IPC_C 20.292,120.659 r270 top
C573 "100nf/0201/25V" FP-CL03-IPC_C 22.547,120.671 r270 top
C574 "100nf/0201/25V" FP-CL03-IPC_C 27.428,119.646 r180 top
C575 "47ut 2220 50V" CAPC2220(5750)230_N 34.098,14.848 r270 top
C576 "47ut 2220 50V" CAPC2220(5750)230_N 16.534,7.655 r90 top
C577 "47ut 2220 50V" CAPC2220(5750)230_N 34.077,7.534 r90 top
C578 "47ut 2220 50V" CAPC2220(5750)230_N 40.07,7.566 r90 top
C579 "47ut 2220 50V" CAPC2220(5750)230_N 22.203,7.526 r90 top
C580 "47ut 2220 50V" CAPC2220(5750)230_N 28.134,14.869 r270 top
C581 "47ut 2220 50V" CAPC2220(5750)230_N 22.133,14.85 r270 top
C582 "47ut 2220 50V" CAPC2220(5750)230_N 16.516,14.826 r270 top
C583 "47ut 2220 50V" CAPC2220(5750)230_N 40.082,15.05 r270 top
C584 "47ut 2220 50V" CAPC2220(5750)230_N 28.146,7.533 r90 top
C585 "CAP 1uF 100V 1206(3216)" CAPC1206(3216)190_M 44.815,14.258 r270 top value=1uF
C586 "1000pf 0603 50V" FP-C0603C-CF-MFG 29.163,25.963 r90 top value="1,000 pF"
C587 "1000pf 0603 50V" FP-C0603C-CF-MFG 35.797,42.178 r90 top value="1,000 pF"
C588 "CAP 1uF 100V 1206(3216)" CAPC1206(3216)190_M 34.01,36.08 r90 top value=1uF
C589 "CAP 1uF 100V 1206(3216)" CAPC1206(3216)190_M 27.815,43.225 r270 top value=1uF
C590 "100nf/0603" CAPC1608X92X38ML15T08 87.803,115.49 r90 top
C591 "0.1uf 0603 16V" CAPC1608X90X35NL15T15 60.074,114.526 r90 top
C592 "100nf/0603" CAPC1608X92X38ML15T08 51.94,114.803 r0 top
C593 "0.1uf 0402 16V" FP-C0402-BB-MFG 241.181,45.963 r270 top value="0.10 μF"
C594 "0.1uf 0402 16V" FP-C0402-BB-MFG 239.897,45.95 r270 top value="0.10 μF"
C595 "0.1uf 0402 16V" FP-C0402-BB-MFG 238.705,45.966 r270 top value="0.10 μF"
C596 "0.1uf 0402 16V" FP-C0402-BB-MFG 237.429,45.95 r270 top value="0.10 μF"
C597 "CAP 22uF 16V 1206(3216)" CAPC1206(3216)190_L 237.178,92.65 r270 top value=22uF
C598 "15pf/0402" FP-C0402-BB-MFG 230.438,45.392 r90 top value="15 pF"
C599 "15pf/0402" FP-C0402-BB-MFG 235.984,45.276 r270 top value="15 pF"
C600 "CAP 22uF 16V 1206(3216)" CAPC1206(3216)190_L 239.138,92.65 r270 top value=22uF
C601 "0.47UF 10V X7R 0805" FP-C0805C-DN-MFG 236.606,87.047 r0 top value="0.47 μF"
C602 "100nf 10V 0402" CAPC1005X55X25LL05T10 241.034,68.551 r180 top
C603 "2.2 nF 0402" FP-CGA2B-IPC_B 237.515,78.442 r180 top
C604 "6.8μF 35V 0805" FP-C2012-125-0_2-IPC_B 237.441,74.285 r180 top
C605 "6.8μF 35V 0805" FP-C2012-125-0_2-IPC_B 237.518,76.6 r180 top
C606 "15pf/0402" FP-C0402-BB-MFG 224.97,62.964 r90 top value="15 pF"
C607 "0.1uf 0402 16V" FP-C0402-BB-MFG 235.032,63.968 r270 top value="0.10 μF"
C608 "0.1uf 0402 16V" FP-C0402-BB-MFG 233.748,63.948 r270 top value="0.10 μF"
C609 "0.1uf 0402 16V" FP-C0402-BB-MFG 232.468,63.96 r270 top value="0.10 μF"
C610 "0.1uf 0402 16V" FP-C0402-BB-MFG 231.188,63.949 r270 top value="0.10 μF"
C611 "10uf/0402" CAPC0402(1005)60_L 264.178,56.598 r270 bottom value=10µF
C612 "100nf/0201" FP-CL03-IPC_C 147.953,77.155 r0 bottom
C613 "1uf/0201" FP-CC0201-BA-MFG 261.385,48.725 r270 bottom value="1 uF"
C614 "1uf/0201" FP-CC0201-BA-MFG 259.443,48.721 r270 bottom value="1 uF"
C615 "100nf/0201" FP-CL03-IPC_C 260.464,48.724 r90 bottom
C616 "100nf/0201" FP-CL03-IPC_C 263.232,48.761 r90 bottom
C617 "100nf/0201" FP-CL03-IPC_C 262.336,48.739 r90 bottom
C618 "15pf/0402" FP-C0402-BB-MFG 227.809,65.524 r180 top value="15 pF"
C619 "1uf 0603 25V" CAPC1608X95X35NL15T15 265.403,55.994 r90 bottom
C620 "CAP 22uF 16V 1206(3216)" CAPC1206(3216)190_L 246.182,71.54 r180 top value=22uF
C621 "CAP 22uF 16V 1206(3216)" CAPC1206(3216)190_L 246.178,73.506 r180 top value=22uF
C622 "CAP 22uF 16V 1206(3216)" CAPC1206(3216)190_L 246.143,75.549 r180 top value=22uF
C623 "CAP 22uF 16V 1206(3216)" CAPC1206(3216)190_L 246.141,77.52 r180 top value=22uF
C624 "CAP 22uF 16V 1206(3216)" CAPC1206(3216)190_L 246.102,79.491 r180 top value=22uF
C625 "CAP 22uF 16V 1206(3216)" CAPC1206(3216)190_L 246.081,81.448 r180 top value=22uF
C626 "0.47UF 10V X7R 0805" FP-C0805C-DN-MFG 243.216,67.888 r270 top value="0.47 μF"
C627 "10uf/0402" CAPC0402(1005)60_L 248.915,37.255 r270 top value=10µF
C628 "4.7uf/0402" FP-CC0402-MFG 250.125,37.284 r90 top value="4.7 uF"
C629 "100nf/0201" FP-CL03-IPC_C 247.77,37.202 r90 top
C630 "0.1uf 0402 16V" FP-C0402-BB-MFG 265.726,41.332 r0 top value="0.10 μF"
C631 "0.1uf 0402 16V" FP-C0402-BB-MFG 265.742,40.018 r0 top value="0.10 μF"
C632 "100nf/0201" FP-CL03-IPC_C 146.521,76.901 r0 bottom
C633 "0.1uf 0402 16V" FP-C0402-BB-MFG 265.748,38.75 r0 top value="0.10 μF"
C634 "0.1uf 0402 16V" FP-C0402-BB-MFG 265.748,37.482 r0 top value="0.10 μF"
C635 "CAP 22uF 16V 1206(3216)" CAPC1206(3216)190_L 282.355,58.831 r270 top value=22uF
C636 "CAP 22uF 16V 1206(3216)" CAPC1206(3216)190_L 280.374,58.822 r270 top value=22uF
C637 "10uf/0603" FP-CC0603-DC-MFG 66.008,51.22 r90 top
C638 "CAP 22uF 16V 1206(3216)" CAPC1206(3216)190_L 278.418,58.822 r270 top value=22uF
C639 "CAP 22uF 16V 1206(3216)" CAPC1206(3216)190_L 276.461,58.83 r270 top value=22uF
C640 "CAP 22uF 16V 1206(3216)" CAPC1206(3216)190_L 274.509,58.827 r270 top value=22uF
C641 "C0402C104M3PAC7867" FP-C0402-BB-MFG 61.087,121.153 r270 top value="0.10 μF"
C642 "1uf 16V 0402" FP-CC0402-MFG 62.399,121.151 r270 top value="1 uF"
C643 "1uf 16V 0402" FP-CC0402-MFG 57.101,121.016 r270 top value="1 uF"
C644 "C0402C104M3PAC7867" FP-C0402-BB-MFG 55.774,120.998 r270 top value="0.10 μF"
C645 "C0402C104M3PAC7867" FP-C0402-BB-MFG 66.203,121.734 r90 top value="0.10 μF"
C646 "1uf 16V 0402" FP-CC0402-MFG 64.88,121.726 r90 top value="1 uF"
C647 "1uf 16V 0402" FP-CC0402-MFG 70.142,124.397 r180 top value="1 uF"
C648 "C0402C104M3PAC7867" FP-C0402-BB-MFG 70.128,119.539 r180 top value="0.10 μF"
C649 "1uf/0402" FP-C0402C-BB-IPC_B 242.622,31.767 r180 top
C650 "1uf/0402" FP-C0402C-BB-IPC_B 242.484,36.424 r180 top
C651 "0.1uf / 0201" FP-CC0201-BB-MFG 242.722,30.558 r0 top
C652 "0.1uf / 0201" FP-CC0201-BB-MFG 242.311,37.636 r0 top
C653 "1uf/0402" FP-C0402C-BB-IPC_B 239.781,29.96 r90 top
C654 "0.1uf / 0201" FP-CC0201-BB-MFG 236.89,30.396 r270 top
C655 "10uf/0603" FP-CC0603-DC-MFG 234.408,48.941 r270 top
C656 "1uf/0402" FP-C0402C-BB-IPC_B 232.861,49.119 r90 top
C657 "0.1uf / 0201" FP-CC0201-BB-MFG 235.786,49.537 r270 top
C658 "10uf/0603" FP-CC0603-DC-MFG 232.81,56.563 r270 bottom
C659 "10uf/0603" FP-CC0603-DC-MFG 237.482,53.356 r0 top
C660 "10uf/0603" FP-CC0603-DC-MFG 239.488,55.179 r0 top
C661 "1uf/0402" FP-C0402C-BB-IPC_B 228.9,54.292 r90 bottom
C662 "0.1uf / 0201" FP-CC0201-BB-MFG 234.675,59.441 r270 bottom
C663 "1uf/0402" FP-C0402C-BB-IPC_B 237.33,51.849 r180 top
C664 "1uf/0402" FP-C0402C-BB-IPC_B 239.326,56.698 r180 top
C665 "0.1uf / 0201" FP-CC0201-BB-MFG 237.312,50.617 r0 top
C666 "0.1uf / 0201" FP-CC0201-BB-MFG 239.326,57.901 r0 top
C667 "0805, 10uF 50V" FP-GRM21B-0_2-e0_2_0_7-IPC_C 241.423,97.621 r0 top
C668 "0805, 10uF 50V" FP-GRM21B-0_2-e0_2_0_7-IPC_C 241.416,99.891 r0 top
C669 "100nF 0603" FP-CGA3E-0_3-0_1-IPC_A 241.641,102.377 r0 top
C670 "56PF 10V 0402" FP-C0402-BB-MFG 237.787,101.086 r0 top value="56 pF"
C671 "GRM21BR61A226ME44L" FP-GRM21B-0_2-e0_2_0_7-IPC_C 243.096,115.322 r90 top
C672 "GRM21BR61A226ME44L" FP-GRM21B-0_2-e0_2_0_7-IPC_C 247.635,115.3 r90 top
C673 "GRM21BR61A226ME44L" FP-GRM21B-0_2-e0_2_0_7-IPC_C 245.366,115.317 r90 top
C674 "GRM188R72A104KA35D" FP-GRM188-0_1-e0_2_0_5-IPC_B 241.12,115.258 r90 top
C675 "0805, 10uF 50V" FP-GRM21B-0_2-e0_2_0_7-IPC_C 227.437,98.482 r0 top
C676 "0805, 10uF 50V" FP-GRM21B-0_2-e0_2_0_7-IPC_C 227.498,100.736 r0 top
C677 "100nF 0603" FP-CGA3E-0_3-0_1-IPC_A 228.075,103.059 r0 top
C678 "56PF 10V 0402" FP-C0402-BB-MFG 223.052,99.213 r0 top value="56 pF"
C679 "GRM21BR61A226ME44L" FP-GRM21B-0_2-e0_2_0_7-IPC_C 231.473,114.683 r90 top
C680 "GRM21BR61A226ME44L" FP-GRM21B-0_2-e0_2_0_7-IPC_C 233.724,114.682 r90 top
C681 "GRM21BR61A226ME44L" FP-GRM21B-0_2-e0_2_0_7-IPC_C 229.22,114.676 r90 top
